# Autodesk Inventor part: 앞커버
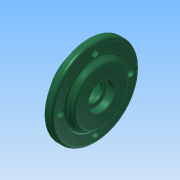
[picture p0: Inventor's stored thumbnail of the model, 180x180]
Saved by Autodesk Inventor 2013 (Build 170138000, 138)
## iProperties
Created: 2015-11
Part Number: 앞커버
Material: 알루미늄 6061
Document SubType Name: Modeling
Designer: mduedu
Density: 2.71 g/cm^3
Mass: 290.026 g
Surface Area: 234.647 cm^2
Volume: 107.021 cm^3
Author: mduedu
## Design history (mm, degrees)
sketch "스케치1"
  geometry: C1 r 50 at (0, 0); 1 further point
  constraints: 1 centre point, 1 coincident
  dimensions: "d57" = 100 diameter of C1
extrude "돌출1" new body sketch "스케치1" distance "d3" = 8; taper "d4" = 0 deg
sketch "스케치2"
  geometry: C1 r 35 at (0, 0); 1 further point
  constraints: 1 centre point, 1 coincident
  dimensions: "d5" = 70 diameter of C1
extrude "돌출2" join sketch "스케치2" distance "d6" = 7; taper "d7" = -30 deg
sketch "스케치3" dims "d58" = 80
  geometry: 3 further points
  constraints: 2 vertical alignment, 1 coincident, 2 other
hole "구멍1" sketch "스케치3" at (0, 40) diameter "d11" = 4.5; stored, may be unused: countersink angle "d15" = 90 deg, drill point angle "d17" = 118 deg; dims "d12" = 6, "d13" = 8, "d14" = 4.4, "d16" = 8
sketch "스케치4"
  geometry: C1 r 35 at (0, 0); 1 further point
  constraints: 1 centre point, 1 coincident
  dimensions: "d21" = 70 diameter of C1
extrude "돌출3" join sketch "스케치4" distance "d23" = 12; taper "d24" = 0 deg
hole "구멍2" diameter "d27" = 30; stored, may be unused: countersink angle "d31" = 90 deg, drill point angle "d33" = 0 deg; dims "d25" = 10, "d26" = 10, "d28" = 6, "d29" = 40, "d30" = 12, "d32" = 15
fillet "모깎기3" dims "d36" = 3
fillet "모깎기4" dims "d37" = 3
fillet "모깎기5" dims "d38" = 0.3
chamfer "모따기1" distance "d39" = 1; stored, may be unused: second distance "d40" = 2, angle "d41" = 45 deg
hole "구멍3" diameter "d44" = 20; stored, may be unused: countersink angle "d48" = 90 deg, drill point angle "d50" = 118 deg; dims "d45" = 6, "d46" = 30, "d47" = 8.3, "d49" = 8, "d59" = 10, "d60" = 10
fillet "모깎기6" dims "d51" = 0.3
chamfer "모따기2" distance "d52" = 0.8; stored, may be unused: second distance "d53" = 2, angle "d54" = 30 deg
node "솔리드1"
pattern_circular "원형 패턴1" dims angle "d19" = 360 deg
